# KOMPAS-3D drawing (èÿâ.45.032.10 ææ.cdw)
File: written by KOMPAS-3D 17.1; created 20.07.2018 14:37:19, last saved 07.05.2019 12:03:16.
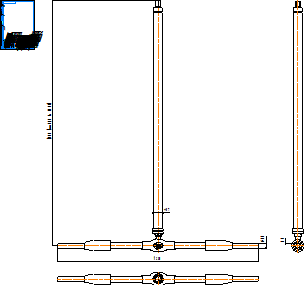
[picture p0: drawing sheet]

Sheet 1: A4, portrait

Title block, sheet 1: name: КШГ.45.032.10 СС; material: Внимание! Данный продукт является объектом авторского права ООО «Торговый Дом АДЛ». / Запрещается изменение, копирование, распространение / (в том числе путем копирования на другие сайты и ресурсы в Интернете) / или любое иное использование информации и объектов без предварительного / согласия правообладателя (ООО «Торговый Дом АДЛ»).; sheets: 1; organisation: ООО "Торговый дом АДЛ"; sheet format: A4; stored path: C:\Users\tra\Desktop\2д чертежи\Шаровые краны БИВАЛ\КШ_Бивал_серия_44_45_55\KOMPAS 2D\КШГ.45.032.10 СС.cdw

Views: Вид 1, Проекционный вид 2, Проекционный вид 3
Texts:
  kka
  adl
  (от 245 до 5000)
Dimensions and other numbers on the sheet: 1230; 1500; 57; 32; 2,9; 1:1; 1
